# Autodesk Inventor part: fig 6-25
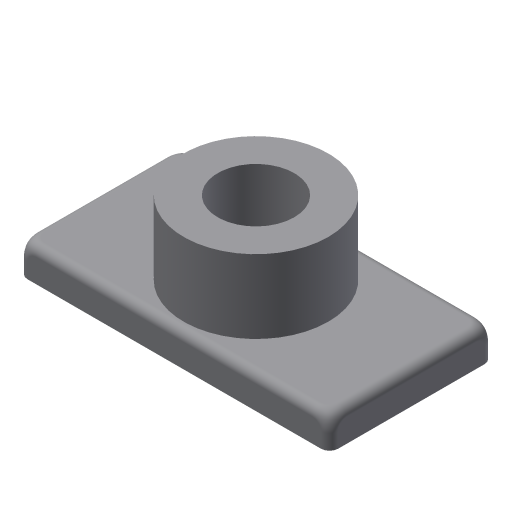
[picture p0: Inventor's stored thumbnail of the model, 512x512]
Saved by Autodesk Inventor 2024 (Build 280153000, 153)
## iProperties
Created: 2004-05
Part Number: fig 6-25
Document SubType Name: Modeling
Designer: CADCIM Technologies
Manufacturer: Standard
Standards Organization: Custom
Density: 1 g/cm^3
Material: Generic
Appearance: Default
Author: CADCIM Technologies
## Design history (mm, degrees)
sketch "Sketch1"
  geometry: L1 (-39.276, -18.692)-(33.721, -18.692); L2 (33.721, -18.692)-(33.721, 19.728); L3 (33.721, 19.728)-(-39.276, 19.728); L4 (-39.276, 19.728)-(-39.276, -18.692)
  constraints: 8 end point, 2 parallel, 1 horizontal, 1 perpendicular
extrude "Extrusion1" new body sketch "Sketch1" distance "d0" = 7.5; taper "d1" = 0 deg
sketch "Sketch2"
  geometry: C1 r 17 at (-2.778, 0.518)
  constraints: 1 centre point
  dimensions: "d16" = 34 diameter of C1
extrude "Extrusion2" join sketch "Sketch2" distance "d3" = 17.25; taper "d4" = 0 deg
hole "Hole1" diameter "d8" = 18; stored, may be unused: countersink angle "d12" = 90 deg, drill point angle "d14" = 118 deg; dims "d6" = 10, "d7" = 10, "d9" = 6, "d10" = 4, "d11" = 2, "d13" = 8
fillet "Fillet4" dims "d17" = 2
body "Solid1"
